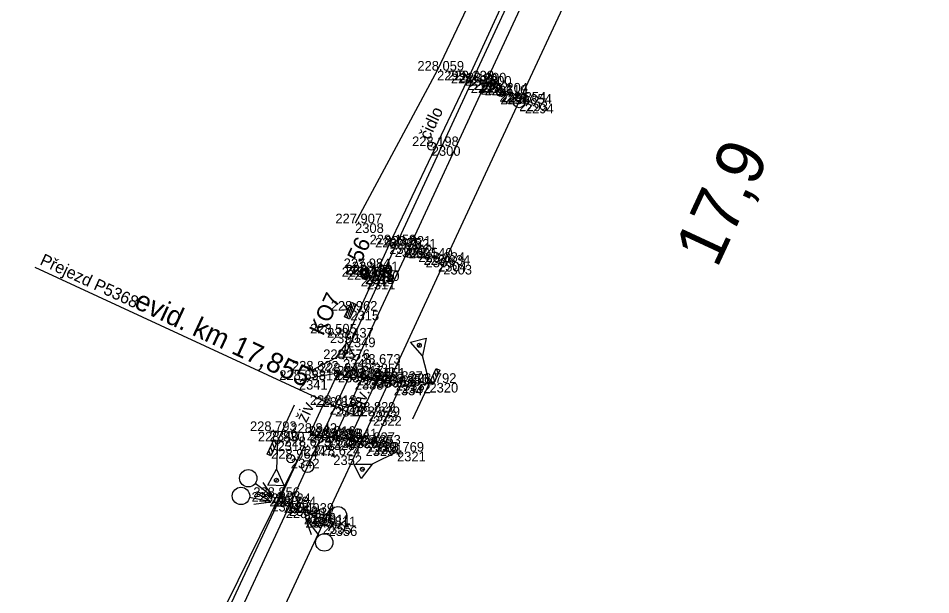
# Model space of a CAD drawing. Extents: x -644425 to -644066, y -1046154 to -1045540.
# Drawn here: x -644287.3 to -644173.8, y -1045879.3 to -1045807.6 of the extents above; entities that cross this region are included whole.
import ezdxf

# ---------------------------------------------------------------- set-up
doc = ezdxf.new("R2010")
doc.units = 0
for name, color, linetype in [('Vrstva 1', 7, 'Continuous'), ('Vrstva 11', 7, 'Continuous'), ('Vrstva 12', 7, 'Continuous'), ('Vrstva 23', 7, 'Continuous'), ('Vrstva 27', 7, 'Continuous'), ('Vrstva 3', 7, 'Continuous'), ('Vrstva 4', 7, 'Continuous'), ('Vrstva 49', 7, 'Continuous'), ('Vrstva 50', 7, 'Continuous'), ('Vrstva 51', 7, 'Continuous'), ('Vrstva 60', 7, 'Continuous'), ('Vrstva 61', 7, 'Continuous'), ('Vrstva 62', 7, 'Continuous'), ('Vrstva 7', 7, 'Continuous')]:
    doc.layers.add(name, color=color, linetype=linetype)

msp = doc.modelspace()

# ---------------------------------------------------------------- linework, layer by layer
at = {"layer": 'Vrstva 1'}
for points in [[(-644261.9, -1045886.22), (-644253.57, -1045868.3), (-644247.84, -1045855.91), (-644238.68, -1045836.23), (-644229.25, -1045815.94), (-644223.2, -1045802.86), (-644216.38, -1045788.16), (-644209.48, -1045773.32), (-644199.55, -1045751.95), (-644192.43, -1045736.62), (-644187.91, -1045726.87), (-644178.39, -1045706.38), (-644167.72, -1045683.41), (-644162.73, -1045672.68), (-644153.24, -1045652.21), (-644143.76, -1045631.81), (-644136.16, -1045615.44), (-644132.18, -1045606.85), (-644125.38, -1045592.19), (-644118.95, -1045578.36), (-644111.36, -1045561.99), (-644101.68, -1045541.12)], [(-644257.58, -1045888.2), (-644249.37, -1045870.52), (-644243.12, -1045857.07), (-644234.39, -1045838.24), (-644224.95, -1045817.93), (-644218.68, -1045804.41), (-644212.07, -1045790.2), (-644205.18, -1045775.37), (-644195.28, -1045754.06), (-644188.04, -1045738.48), (-644183.51, -1045728.69), (-644173.98, -1045708.19), (-644163.21, -1045685.03), (-644158.47, -1045674.84), (-644148.94, -1045654.32), (-644139.46, -1045633.91), (-644131.76, -1045617.29), (-644127.6, -1045608.33), (-644121.08, -1045594.3), (-644114.62, -1045580.38), (-644107.04, -1045564.05), (-644097.3, -1045543.08)]]:
    msp.add_lwpolyline(points, dxfattribs=at)
at = {"layer": 'Vrstva 11'}
for p, q in [((-644244.16, -1045839.91), (-644244.47, -1045839.06)), ((-644243.81, -1045839.79), (-644244.12, -1045838.92))]:
    msp.add_line(p, q, dxfattribs=at)
msp.add_circle((-644244.13, -1045839.42), 0.5, dxfattribs=at)
at = {"layer": 'Vrstva 12'}
msp.add_lwpolyline([(-644244.33, -1045838.65), (-644243.41, -1045839.04), (-644243.91, -1045840.1), (-644244.66, -1045839.72), (-644244.33, -1045838.65)], dxfattribs=at)
at = {"layer": 'Vrstva 23'}
msp.add_line((-644244.03, -1045839.46), (-644244.03, -1045839.46), dxfattribs=at)
at = {"layer": 'Vrstva 27'}
for p, q in [((-644245.55, -1045843.88), (-644245.87, -1045843)), ((-644245.4, -1045843.56), (-644245.6, -1045843)), ((-644245.99, -1045844.85), (-644246.32, -1045843.96)), ((-644245.84, -1045844.52), (-644246.17, -1045843.64)), ((-644245.69, -1045844.2), (-644246.02, -1045843.32)), ((-644245.25, -1045843.24), (-644245.28, -1045843.15)), ((-644246.56, -1045844.76), (-644246.61, -1045844.6)), ((-644246.24, -1045844.91), (-644246.47, -1045844.28))]:
    msp.add_line(p, q, dxfattribs=at)
msp.add_lwpolyline([(-644246.66, -1045844.71), (-644245.82, -1045842.9), (-644245.22, -1045843.18), (-644246.06, -1045844.99)], close=True, dxfattribs=at)
msp.add_lwpolyline([(-644246.99, -1045843.82), (-644246.24, -1045843.8), (-644246.71, -1045843.22)], dxfattribs=at)
at = {"layer": 'Vrstva 3'}
for p, q in [((-644255.57, -1045867.12), (-644257.77, -1045865.46)), ((-644255.78, -1045867.73), (-644258.49, -1045867.21)), ((-644254.69, -1045868.33), (-644254.27, -1045867.42)), ((-644254.48, -1045867.88), (-644252.66, -1045868.72)), ((-644252.87, -1045869.17), (-644252.45, -1045868.27)), ((-644251.32, -1045869.1), (-644248.57, -1045869.32)), ((-644251.53, -1045869.75), (-644249.85, -1045871.93)), ((-644250.07, -1045869.64), (-644250.49, -1045870.55)), ((-644248.46, -1045870.94), (-644250.28, -1045870.09)), ((-644248.25, -1045870.48), (-644248.67, -1045871.39))]:
    msp.add_line(p, q, dxfattribs=at)
for points in [[(-644257.64, -1045866.43), (-644255.57, -1045867.12), (-644256.81, -1045865.32)], [(-644257.94, -1045868.02), (-644255.78, -1045867.73), (-644257.68, -1045866.67)], [(-644249.2, -1045868.58), (-644251.32, -1045869.1), (-644249.31, -1045869.95)], [(-644249.72, -1045870.96), (-644251.53, -1045869.75), (-644250.81, -1045871.81)]]:
    msp.add_lwpolyline(points, dxfattribs=at)
for centre in [(-644258.64, -1045864.8), (-644259.55, -1045867), (-644247.49, -1045869.41), (-644249.19, -1045872.79)]:
    msp.add_circle(centre, 1.08, dxfattribs=at)
at = {"layer": 'Vrstva 4'}
for p, q in [((-644245.63, -1045856.88), (-644285.13, -1045838.55)), ((-644237.49, -1045848.46), (-644237.24, -1045848.04)), ((-644246.74, -1045849.02), (-644246.27, -1045849.17)), ((-644251.13, -1045850.71), (-644250.4, -1045852.09)), ((-644235.71, -1045852.06), (-644235.47, -1045852.73)), ((-644235.49, -1045851.58), (-644235.25, -1045852.25)), ((-644235.26, -1045851.12), (-644235.02, -1045851.77)), ((-644236.11, -1045852.93), (-644238.22, -1045857.46)), ((-644236.87, -1045853.12), (-644235.36, -1045852.73)), ((-644235.94, -1045852.55), (-644235.73, -1045853.11)), ((-644255, -1045860.21), (-644252.9, -1045855.67)), ((-644255.18, -1045860.59), (-644255.38, -1045860.03)), ((-644255.62, -1045861.56), (-644255.87, -1045860.89)), ((-644254.22, -1045860.24), (-644255.78, -1045860.18)), ((-644255.4, -1045861.07), (-644255.64, -1045860.41)), ((-644239.79, -1045862.19), (-644240.48, -1045860.79)), ((-644255.85, -1045862.02), (-644256.09, -1045861.37)), ((-644244.22, -1045863.75), (-644244.69, -1045863.59)), ((-644254.96, -1045864.88), (-644255.32, -1045865.22))]:
    msp.add_line(p, q, dxfattribs=at)
for points in [[(-644104.83, -1045544.56), (-644115.41, -1045567.25), (-644126.59, -1045591.73), (-644133.49, -1045605.95), (-644145.84, -1045632.82), (-644153.92, -1045650.61), (-644164.19, -1045672.05), (-644168.98, -1045682.75), (-644179.4, -1045705.41), (-644189.24, -1045726.17), (-644192.71, -1045732.79), (-644195.84, -1045739.43), (-644200.88, -1045751.59), (-644210.7, -1045773.33), (-644219.76, -1045791.51), (-644230.98, -1045815.66), (-644240.43, -1045836.08), (-644246.86, -1045849.97)], [(-644195.84, -1045739.43), (-644197.57, -1045741.51), (-644202.01, -1045751.15), (-644211.62, -1045772.79), (-644220.34, -1045791.21), (-644231.43, -1045815.29), (-644241.11, -1045835.69), (-644246.39, -1045847.29), (-644246.86, -1045849.97)], [(-644236.11, -1045852.93), (-644236.99, -1045849.56), (-644238.45, -1045847.87), (-644236.52, -1045847.36), (-644236.99, -1045849.56)], [(-644250.77, -1045851.4), (-644247.7, -1045849.77), (-644246.39, -1045847.95), (-644245.44, -1045849.71), (-644247.7, -1045849.77)], [(-644245.15, -1045852.02), (-644245.4, -1045852.56), (-644247.5, -1045851.67), (-644250.96, -1045859.15), (-644248.92, -1045860.08), (-644248.65, -1045859.52), (-644247.96, -1045859.8), (-644244.47, -1045852.34), (-644245.15, -1045852.02)], [(-644246.04, -1045859.84), (-644244.06, -1045860.83), (-644243.76, -1045860.28), (-644243.03, -1045860.61), (-644239.54, -1045853.02), (-644240.29, -1045852.68), (-644240.55, -1045853.27), (-644242.55, -1045852.28), (-644246.04, -1045859.84)], [(-644251.69, -1045860.81), (-644263.45, -1045886.15), (-644273.54, -1045907.57), (-644283.07, -1045928.33), (-644294.82, -1045954.12), (-644305.08, -1045975.98), (-644315.38, -1045998.26), (-644326.07, -1046020.88), (-644336.11, -1046042.31), (-644345.1, -1046062.23), (-644350.82, -1046072.61), (-644354.59, -1046081.15), (-644360.02, -1046093.18), (-644374.01, -1046123.67), (-644385.41, -1046148.39)], [(-644251.69, -1045860.81), (-644264.07, -1045885.99), (-644274.03, -1045907.35), (-644283.58, -1045928.21), (-644295.44, -1045953.83), (-644305.74, -1045975.8), (-644316, -1045997.95), (-644326.85, -1046020.58), (-644337.1, -1046041.88), (-644346.2, -1046061.79), (-644350.38, -1046071.13), (-644350.82, -1046072.61)], [(-644255, -1045860.21), (-644255.12, -1045863.68), (-644254.2, -1045865.72), (-644256.2, -1045865.66), (-644255.12, -1045863.68)], [(-644240.14, -1045861.49), (-644243.25, -1045863.04), (-644244.6, -1045864.82), (-644245.5, -1045863.03), (-644243.25, -1045863.04)]]:
    msp.add_lwpolyline(points, dxfattribs=at)
for points in [[(-644234.82, -1045851.33), (-644235.66, -1045853.14), (-644236.11, -1045852.93), (-644235.27, -1045851.12)], [(-644256.29, -1045861.81), (-644255.45, -1045860), (-644255, -1045860.21), (-644255.84, -1045862.02)]]:
    msp.add_lwpolyline(points, close=True, dxfattribs=at)
for centre in [(-644237.37, -1045848.25), (-644246.51, -1045849.1), (-644244.45, -1045863.67), (-644255.14, -1045865.05)]:
    msp.add_circle(centre, 0.248, dxfattribs=at)
at = {"layer": 'Vrstva 49'}
for p, q in [((-644227.2, -1045817.3), (-644227.37, -1045816.83)), ((-644227.52, -1045817.15), (-644227.05, -1045816.98)), ((-644236.82, -1045837.42), (-644236.35, -1045837.25)), ((-644236.5, -1045837.57), (-644236.67, -1045837.1)), ((-644248.72, -1045846.87), (-644248.25, -1045846.7)), ((-644248.4, -1045847.02), (-644248.57, -1045846.55)), ((-644243.28, -1045850.63), (-644242.81, -1045850.46)), ((-644242.96, -1045850.78), (-644243.13, -1045850.31)), ((-644248.3, -1045862.04), (-644247.84, -1045861.87)), ((-644247.98, -1045862.19), (-644248.16, -1045861.72))]:
    msp.add_line(p, q, dxfattribs=at)
msp.add_lwpolyline([(-644196.58, -1045738.95), (-644199.1, -1045740.02), (-644204.21, -1045749.96), (-644213.44, -1045771.93), (-644223.74, -1045790.03), (-644235.16, -1045814.07), (-644245.36, -1045833.07)], dxfattribs=at)
at = {"layer": 'Vrstva 50'}
msp.add_line((-644235.84, -1045823.51), (-644235.8, -1045823.42), dxfattribs=at)
msp.add_circle((-644235.82, -1045823.47), 0.5, dxfattribs=at)
at = {"layer": 'Vrstva 51'}
for points in [[(-644252.34, -1045852.56), (-644247.5, -1045851.67), (-644250.96, -1045859.15), (-644255.98, -1045858.92)], [(-644244.47, -1045852.34), (-644242.55, -1045852.28), (-644246.04, -1045859.84), (-644247.96, -1045859.8), (-644244.47, -1045852.34)]]:
    msp.add_lwpolyline(points, dxfattribs=at)
at = {"layer": 'Vrstva 60'}
for p, q in [((-644235.16, -1045814.07), (-644235.16, -1045814.07)), ((-644231.43, -1045815.29), (-644231.43, -1045815.29)), ((-644230.98, -1045815.66), (-644230.98, -1045815.66)), ((-644229.9, -1045815.54), (-644229.9, -1045815.54)), ((-644229.25, -1045815.94), (-644229.25, -1045815.94)), ((-644227.21, -1045816.8), (-644227.21, -1045816.8)), ((-644227.28, -1045817.07), (-644227.28, -1045817.07)), ((-644224.95, -1045817.93), (-644224.95, -1045817.93)), ((-644224.24, -1045818.19), (-644224.24, -1045818.19)), ((-644235.82, -1045823.47), (-644235.82, -1045823.47)), ((-644245.36, -1045833.07), (-644245.36, -1045833.07)), ((-644241.11, -1045835.69), (-644241.11, -1045835.69)), ((-644240.43, -1045836.08), (-644240.43, -1045836.08)), ((-644239.33, -1045835.86), (-644239.33, -1045835.86)), ((-644238.68, -1045836.23), (-644238.68, -1045836.23)), ((-644236.59, -1045837.34), (-644236.59, -1045837.34)), ((-644235.04, -1045837.87), (-644235.04, -1045837.87)), ((-644234.39, -1045838.24), (-644234.39, -1045838.24)), ((-644244.33, -1045838.65), (-644244.33, -1045838.65)), ((-644244.13, -1045839.42), (-644244.13, -1045839.42)), ((-644243.41, -1045839.04), (-644243.41, -1045839.04)), ((-644244.66, -1045839.72), (-644244.66, -1045839.72)), ((-644243.91, -1045840.1), (-644243.91, -1045840.1)), ((-644245.94, -1045843.94), (-644245.94, -1045843.94)), ((-644248.49, -1045846.78), (-644248.49, -1045846.78)), ((-644246.39, -1045847.29), (-644246.39, -1045847.29)), ((-644246.86, -1045849.97), (-644246.86, -1045849.97)), ((-644243.05, -1045850.55), (-644243.05, -1045850.55)), ((-644250.77, -1045851.4), (-644250.77, -1045851.4)), ((-644247.5, -1045851.67), (-644247.5, -1045851.67)), ((-644245.15, -1045852.02), (-644245.15, -1045852.02)), ((-644252.34, -1045852.56), (-644252.34, -1045852.56)), ((-644245.4, -1045852.56), (-644245.4, -1045852.56)), ((-644244.47, -1045852.34), (-644244.47, -1045852.34)), ((-644242.55, -1045852.28), (-644242.55, -1045852.28)), ((-644240.55, -1045853.27), (-644240.55, -1045853.27)), ((-644240.29, -1045852.68), (-644240.29, -1045852.68)), ((-644239.54, -1045853.02), (-644239.54, -1045853.02)), ((-644236.11, -1045852.93), (-644236.11, -1045852.93)), ((-644248.53, -1045855.67), (-644248.53, -1045855.67)), ((-644247.84, -1045855.91), (-644247.84, -1045855.91)), ((-644243.68, -1045856.51), (-644243.68, -1045856.51)), ((-644243.12, -1045857.07), (-644243.12, -1045857.07)), ((-644255.98, -1045858.92), (-644255.98, -1045858.92)), ((-644250.96, -1045859.15), (-644250.96, -1045859.15)), ((-644248.92, -1045860.08), (-644248.92, -1045860.08)), ((-644248.65, -1045859.52), (-644248.65, -1045859.52)), ((-644247.96, -1045859.8), (-644247.96, -1045859.8)), ((-644246.04, -1045859.84), (-644246.04, -1045859.84)), ((-644255, -1045860.21), (-644255, -1045860.21)), ((-644251.69, -1045860.81), (-644251.69, -1045860.81)), ((-644244.06, -1045860.83), (-644244.06, -1045860.83)), ((-644243.76, -1045860.28), (-644243.76, -1045860.28)), ((-644243.03, -1045860.61), (-644243.03, -1045860.61)), ((-644248.07, -1045861.95), (-644248.07, -1045861.95)), ((-644240.14, -1045861.49), (-644240.14, -1045861.49)), ((-644253.35, -1045862.36), (-644253.35, -1045862.36)), ((-644255.78, -1045867.73), (-644255.78, -1045867.73)), ((-644255.57, -1045867.12), (-644255.57, -1045867.12)), ((-644254.22, -1045867.89), (-644254.22, -1045867.89)), ((-644253.57, -1045868.3), (-644253.57, -1045868.3)), ((-644251.32, -1045869.1), (-644251.32, -1045869.1)), ((-644251.53, -1045869.75), (-644251.53, -1045869.75)), ((-644249.37, -1045870.52), (-644249.37, -1045870.52)), ((-644248.66, -1045870.78), (-644248.66, -1045870.78))]:
    msp.add_line(p, q, dxfattribs=at)
at = {"layer": 'Vrstva 62'}
for p, q in [((-644229.9, -1045815.54), (-644229.9, -1045815.54)), ((-644224.24, -1045818.19), (-644224.24, -1045818.19)), ((-644239.33, -1045835.86), (-644239.33, -1045835.86)), ((-644235.04, -1045837.87), (-644235.04, -1045837.87)), ((-644248.53, -1045855.67), (-644248.53, -1045855.67)), ((-644243.68, -1045856.51), (-644243.68, -1045856.51)), ((-644254.22, -1045867.89), (-644254.22, -1045867.89)), ((-644248.66, -1045870.78), (-644248.66, -1045870.78))]:
    msp.add_line(p, q, dxfattribs=at)
at = {"layer": 'Vrstva 7'}
for p, q in [((-644227.23, -1045816.85), (-644227.19, -1045816.76)), ((-644253.38, -1045862.41), (-644253.33, -1045862.32))]:
    msp.add_line(p, q, dxfattribs=at)
for centre, radius in [((-644227.21, -1045816.8), 0.5), ((-644224.95, -1045817.93), 0.75), ((-644253.35, -1045862.36), 0.5), ((-644251.27, -1045863.33), 0.75)]:
    msp.add_circle(centre, radius, dxfattribs=at)

# ---------------------------------------------------------------- texts
at = {"layer": 'Vrstva 11'}
msp.add_text('56', height=2, rotation=65.0558, dxfattribs=at).set_placement((-644244.62, -1045838.09))
at = {"layer": 'Vrstva 27'}
msp.add_text('KO7', height=2, rotation=65.0558, dxfattribs=at).set_placement((-644249.34, -1045847.18))
at = {"layer": 'Vrstva 4'}
for s, height, rotation, p in [('Přejezd P5368', 1.5, 335.1571, (-644284.67, -1045838.15)), ('evid. km 17,855', 2.5, 334.9697, (-644273, -1045843.53))]:
    msp.add_text(s, height=height, rotation=rotation, dxfattribs=at).set_placement(p)
at = {"layer": 'Vrstva 50'}
msp.add_text('čidlo', height=1.5, rotation=65.0723, dxfattribs=at).set_placement((-644236.11, -1045822.77))
at = {"layer": 'Vrstva 51'}
for rotation, p in [(65.1893, (-644244.72, -1045856.67)), (65.1594, (-644251.42, -1045857.99))]:
    msp.add_text('živ.', height=1.5, rotation=rotation, dxfattribs=at).set_placement(p)
at = {"layer": 'Vrstva 60'}
for s, p in [('2299', (-644235.16, -1045815.27)), ('2298', (-644231.43, -1045816.49)), ('2297', (-644230.98, -1045816.86)), ('2292', (-644229.9, -1045816.74)), ('2291', (-644229.25, -1045817.14)), ('2295', (-644227.21, -1045818)), ('2296', (-644227.28, -1045818.27)), ('2293', (-644224.95, -1045819.12)), ('2294', (-644224.24, -1045819.39)), ('2300', (-644235.82, -1045824.67)), ('2308', (-644245.36, -1045834.27)), ('2307', (-644241.11, -1045836.89)), ('2306', (-644240.43, -1045837.28)), ('2302', (-644239.33, -1045837.06)), ('2301', (-644238.68, -1045837.43)), ('2305', (-644236.59, -1045838.54)), ('2304', (-644235.04, -1045839.07)), ('2303', (-644234.39, -1045839.44)), ('2309', (-644244.33, -1045839.85)), ('2313', (-644244.13, -1045840.62)), ('2314', (-644244.03, -1045840.66)), ('2310', (-644243.41, -1045840.24)), ('2312', (-644244.66, -1045840.92)), ('2311', (-644243.91, -1045841.3)), ('2315', (-644245.94, -1045845.14)), ('2350', (-644248.49, -1045847.98)), ('2349', (-644246.39, -1045848.49)), ('2348', (-644246.86, -1045851.17)), ('2351', (-644243.05, -1045851.75)), ('2319', (-644250.77, -1045852.6)), ('2339', (-644247.5, -1045852.87)), ('2337', (-644245.15, -1045853.22)), ('2341', (-644252.34, -1045853.76)), ('2338', (-644245.4, -1045853.76)), ('2336', (-644244.47, -1045853.54)), ('2335', (-644242.55, -1045853.48)), ('2334', (-644240.55, -1045854.47)), ('2333', (-644240.29, -1045853.88)), ('2332', (-644239.54, -1045854.21)), ('2320', (-644236.11, -1045854.13)), ('2317', (-644248.53, -1045856.87)), ('2316', (-644247.84, -1045857.11)), ('2323', (-644243.68, -1045857.71)), ('2322', (-644243.12, -1045858.27)), ('2340', (-644255.98, -1045860.12)), ('2324', (-644250.96, -1045860.35)), ('2325', (-644248.92, -1045861.28)), ('2326', (-644248.65, -1045860.72)), ('2327', (-644247.96, -1045861)), ('2328', (-644246.04, -1045861.04)), ('2318', (-644255, -1045861.41)), ('2347', (-644251.69, -1045862.01)), ('2329', (-644244.06, -1045862.03)), ('2330', (-644243.76, -1045861.48)), ('2331', (-644243.03, -1045861.82)), ('2342', (-644253.35, -1045863.56)), ('2352', (-644248.07, -1045863.15)), ('2321', (-644240.14, -1045862.69)), ('2344', (-644255.78, -1045868.93)), ('2343', (-644255.57, -1045868.32)), ('2354', (-644254.22, -1045869.09)), ('2353', (-644253.57, -1045869.5)), ('2346', (-644251.32, -1045870.31)), ('2345', (-644251.53, -1045870.95)), ('2355', (-644249.37, -1045871.72)), ('2356', (-644248.66, -1045871.98))]:
    msp.add_text(s, height=1.2, dxfattribs=at).set_placement(p)
at = {"layer": 'Vrstva 61'}
for s, p in [('228.059', (-644237.61, -1045814.07)), ('228.238', (-644233.88, -1045815.29)), ('228.499', (-644233.44, -1045815.66)), ('228.800', (-644232.35, -1045815.54)), ('228.800', (-644231.7, -1045815.94)), ('229.204', (-644229.66, -1045816.8)), ('228.610', (-644229.73, -1045817.07)), ('228.854', (-644227.4, -1045817.93)), ('228.854', (-644226.69, -1045818.19)), ('228.198', (-644238.27, -1045823.47)), ('227.907', (-644247.81, -1045833.07)), ('228.159', (-644243.56, -1045835.69)), ('228.475', (-644242.88, -1045836.08)), ('228.821', (-644241.69, -1045835.86)), ('228.821', (-644241.04, -1045836.23)), ('228.540', (-644239.04, -1045837.34)), ('228.834', (-644237.49, -1045837.87)), ('228.834', (-644236.84, -1045838.24)), ('228.051', (-644247.02, -1045839.72)), ('227.984', (-644246.78, -1045838.65)), ('228.120', (-644246.58, -1045839.42)), ('228.120', (-644246.48, -1045839.46)), ('228.141', (-644245.77, -1045839.04)), ('228.155', (-644246.37, -1045840.1)), ('228.962', (-644248.39, -1045843.94)), ('228.505', (-644250.95, -1045846.78)), ('228.437', (-644248.84, -1045847.29)), ('228.576', (-644249.32, -1045849.97)), ('228.673', (-644245.5, -1045850.55)), ('228.822', (-644253.21, -1045851.4)), ('228.841', (-644249.85, -1045851.67)), ('228.817', (-644247.6, -1045852.02)), ('228.858', (-644254.79, -1045852.56)), ('228.819', (-644247.86, -1045852.56)), ('228.844', (-644246.92, -1045852.34)), ('228.851', (-644244.9, -1045852.28)), ('228.828', (-644243, -1045853.27)), ('228.827', (-644242.74, -1045852.68)), ('228.856', (-644241.99, -1045853.02)), ('228.792', (-644238.56, -1045852.93)), ('228.818', (-644250.98, -1045855.67)), ('228.818', (-644250.29, -1045855.91)), ('228.829', (-644246.14, -1045856.51)), ('228.829', (-644245.58, -1045857.07)), ('228.793', (-644258.43, -1045858.92)), ('228.842', (-644253.41, -1045859.15)), ('228.815', (-644251.38, -1045860.08)), ('228.816', (-644251.1, -1045859.52)), ('228.838', (-644250.41, -1045859.8)), ('228.841', (-644248.4, -1045859.84)), ('228.830', (-644257.45, -1045860.21)), ('228.623', (-644254.15, -1045860.81)), ('228.825', (-644246.52, -1045860.83)), ('228.827', (-644246.21, -1045860.28)), ('228.853', (-644245.48, -1045860.61)), ('228.964', (-644255.8, -1045862.36)), ('228.624', (-644250.52, -1045861.95)), ('228.769', (-644242.59, -1045861.49)), ('228.845', (-644258.24, -1045867.73)), ('228.856', (-644258.02, -1045867.12)), ('228.784', (-644256.67, -1045867.89)), ('228.784', (-644256.02, -1045868.3)), ('228.939', (-644253.78, -1045869.1)), ('228.894', (-644253.98, -1045869.75)), ('228.811', (-644251.73, -1045870.52)), ('228.811', (-644251.02, -1045870.78))]:
    msp.add_text(s, height=1.2, dxfattribs=at).set_placement(p)
at = {"layer": 'Vrstva 7'}
msp.add_text('17,9', height=6, rotation=65.0986, dxfattribs=at).set_placement((-644200.36, -1045838.78))

doc.saveas('drawing.dxf')
